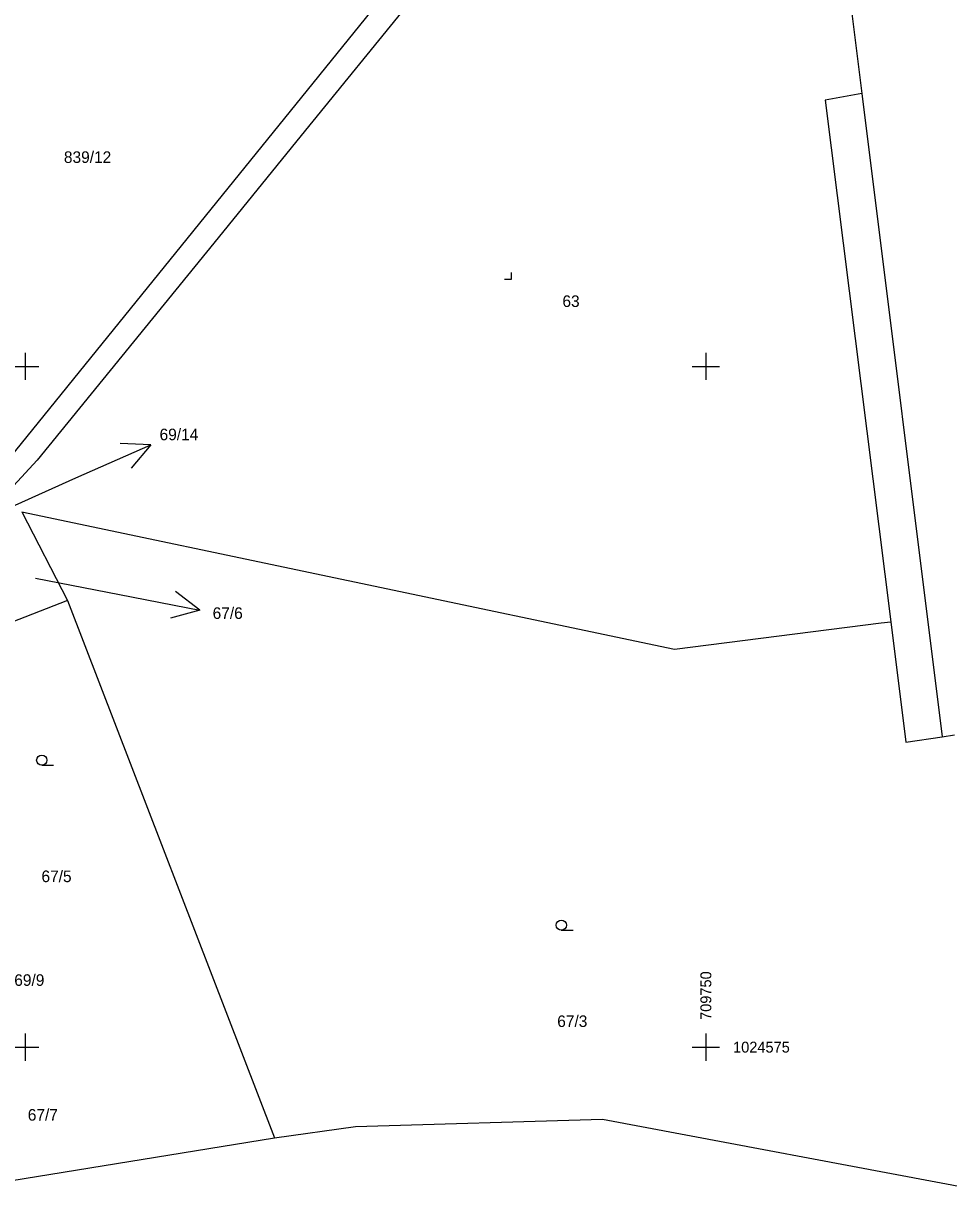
# Model space of a CAD drawing. Extents: x -711081 to -709338, y -1025122 to -1024092.
# Drawn here: x -709775.06 to -709741.09, y -1024580.45 to -1024537.41 of the extents above; entities that cross this region are included whole.
import ezdxf

# ---------------------------------------------------------------- set-up
doc = ezdxf.new("R2010")
doc.units = 0
for name, color, linetype in [('Z_hektometricka_sit', 7, 'Continuous'), ('Z_hektometricka_sit_popis', 7, 'Continuous'), ('Z_katastr_cisla_pozemkova', 7, 'Continuous'), ('Z_katastr_cisla_stavebni', 7, 'Continuous'), ('Z_katastr_hranice', 7, 'Continuous'), ('Z_katastr_parcelni_cislo_odkaz', 7, 'Continuous'), ('Z_katastr_vnitrni_kresba', 7, 'Continuous'), ('Z_katastr_znacky_kultur', 7, 'Continuous')]:
    doc.layers.add(name, color=color, linetype=linetype)

msp = doc.modelspace()

# ---------------------------------------------------------------- linework, layer by layer
at = {"layer": 'Z_hektometricka_sit'}
for p, q in [((-709775, -1024549.5), (-709775, -1024550.5)), ((-709750, -1024549.5), (-709750, -1024550.5)), ((-709775.5, -1024550), (-709774.5, -1024550)), ((-709750.5, -1024550), (-709749.5, -1024550)), ((-709775, -1024574.5), (-709775, -1024575.5)), ((-709750, -1024574.5), (-709750, -1024575.5)), ((-709775.5, -1024575), (-709774.5, -1024575)), ((-709750.5, -1024575), (-709749.5, -1024575))]:
    msp.add_line(p, q, dxfattribs=at)
at = {"layer": 'Z_katastr_hranice'}
for p, q in [((-709758.89, -1024534.18), (-709764.86, -1024541.52)), ((-709744.9, -1024534.89), (-709744.27, -1024539.98)), ((-709744.27, -1024539.98), (-709745.62, -1024540.23)), ((-709745.62, -1024540.23), (-709743.21, -1024559.38)), ((-709764.86, -1024541.52), (-709767.91, -1024545.28)), ((-709767.91, -1024545.28), (-709774.55, -1024553.44)), ((-709774.55, -1024553.44), (-709775.43, -1024554.39)), ((-709775.12, -1024555.34), (-709773.44, -1024558.6)), ((-709775.12, -1024555.34), (-709751.15, -1024560.38)), ((-709773.44, -1024558.6), (-709776.13, -1024559.65)), ((-709773.44, -1024558.6), (-709765.84, -1024578.33)), ((-709751.15, -1024560.38), (-709743.56, -1024559.42)), ((-709743.56, -1024559.42), (-709743.21, -1024559.38)), ((-709743.21, -1024559.38), (-709742.66, -1024563.8)), ((-709742.66, -1024563.8), (-709741.32, -1024563.6)), ((-709741.32, -1024563.6), (-709740.87, -1024563.53)), ((-709762.86, -1024577.91), (-709753.79, -1024577.64)), ((-709753.79, -1024577.64), (-709738.87, -1024580.45)), ((-709765.84, -1024578.33), (-709762.86, -1024577.91)), ((-709777.62, -1024580.24), (-709765.84, -1024578.33))]:
    msp.add_line(p, q, dxfattribs=at)
at = {"layer": 'Z_katastr_parcelni_cislo_odkaz'}
for p, q in [((-709773.13, -1024554.1), (-709770.388, -1024552.879)), ((-709770.388, -1024552.879), (-709771.507, -1024552.829)), ((-709770.388, -1024552.879), (-709771.1, -1024553.744)), ((-709775.36, -1024555.1), (-709773.13, -1024554.1)), ((-709774.62, -1024557.78), (-709771.53, -1024558.38)), ((-709768.584, -1024558.953), (-709769.472, -1024558.27)), ((-709771.53, -1024558.38), (-709768.584, -1024558.953)), ((-709768.584, -1024558.953), (-709769.663, -1024559.253))]:
    msp.add_line(p, q, dxfattribs=at)
at = {"layer": 'Z_katastr_vnitrni_kresba'}
for p, q in [((-709775.75, -1024553.6), (-709760.23, -1024534.42)), ((-709744.27, -1024539.98), (-709741.32, -1024563.6))]:
    msp.add_line(p, q, dxfattribs=at)
at = {"layer": 'Z_katastr_znacky_kultur'}
for p, q in [((-709757.14, -1024546.8), (-709757.14, -1024546.55)), ((-709757.39, -1024546.8), (-709757.14, -1024546.8)), ((-709774.388, -1024564.65), (-709773.951, -1024564.65)), ((-709755.308, -1024570.71), (-709754.871, -1024570.71))]:
    msp.add_line(p, q, dxfattribs=at)
for centre in [(-709774.388, -1024564.462), (-709755.308, -1024570.522)]:
    msp.add_circle(centre, 0.187, dxfattribs=at)

# ---------------------------------------------------------------- texts
at = {"layer": 'Z_hektometricka_sit_popis'}
msp.add_text('709750', height=0.4, rotation=90, dxfattribs=at).set_placement((-709749.8, -1024574))
msp.add_text('1024575', height=0.4, dxfattribs=at).set_placement((-709749, -1024575.2))
at = {"layer": 'Z_katastr_cisla_pozemkova'}
for s, p in [('839/12', (-709773.574, -1024542.53)), ('69/14', (-709770.061, -1024552.714)), ('67/6', (-709768.112, -1024559.275)), ('67/5', (-709774.398, -1024568.94)), ('69/9', (-709775.397, -1024572.75)), ('67/3', (-709755.458, -1024574.26)), ('67/7', (-709774.901, -1024577.699))]:
    msp.add_text(s, height=0.425, dxfattribs=at).set_placement(p)
at = {"layer": 'Z_katastr_cisla_stavebni'}
msp.add_text('63', height=0.425, dxfattribs=at).set_placement((-709755.268, -1024547.82))

doc.saveas('drawing.dxf')
